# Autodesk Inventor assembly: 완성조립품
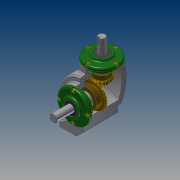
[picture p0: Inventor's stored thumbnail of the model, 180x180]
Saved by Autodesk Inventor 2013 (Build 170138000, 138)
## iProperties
Created: 2017-04
Part Number: 완성조립품
Document SubType Name: Assembly
Designer: Windows7
Author: Windows7
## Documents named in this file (14)
- C:\Users\Windows7\Desktop\470408V1009\완성조립품.iam
- C:\Users\Windows7\Desktop\470408V1009\본체.ipt
- C:\Users\Windows7\Desktop\470408V1009\메인 축.ipt
- 메인 축.ipt
- C:\Users\Windows7\Desktop\470408V1009\베어링 6203.ipt
- C:\Users\Windows7\Desktop\470408V1009\키 5x5.ipt
- C:\Users\Windows7\Desktop\470408V1009\커버.ipt
- C:\Users\Windows7\Desktop\470408V1009\오일실 17 32 8.ipt
- C:\Users\Windows7\Desktop\470408V1009\메인 베벨기어.ipt
- C:\Users\Windows7\Desktop\470408V1009\서브 축.ipt
- 서브 축.ipt
- C:\Users\Windows7\Desktop\470408V1009\키 4x4.ipt
- C:\Users\Windows7\Desktop\470408V1009\서브 베벨기어.ipt
- C:\Users\Windows7\Desktop\470408V1009\볼트 M4.ipt
